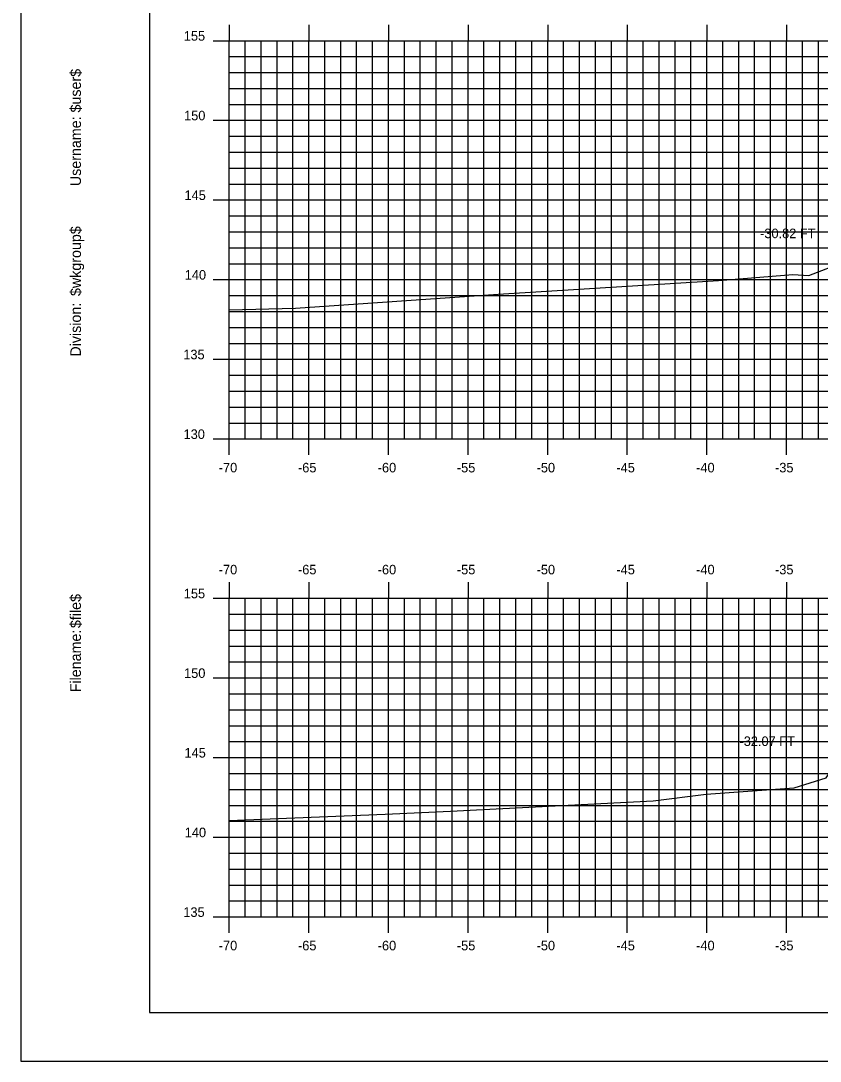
# Model space of a CAD drawing. Extents: x 1143863 to 1144033, y 608981 to 609091.
# Drawn here: x 1143863.5 to 1143913.7, y 608981.3 to 609046.6 of the extents above; entities that cross this region are included whole.
import ezdxf

# ---------------------------------------------------------------- set-up
doc = ezdxf.new("R2010")
doc.units = 0
for name, color, linetype in [('BORDER', 7, 'Continuous'), ('D_Text_Standard', 7, 'Continuous'), ('H_V ANNOTATION', 7, 'Continuous'), ('MAJOR', 7, 'Continuous'), ('MINOR', 7, 'Continuous'), ('PLOT BOUNDARY', 7, 'Continuous'), ('S_Roadway_Centerline', 7, 'Continuous')]:
    doc.layers.add(name, color=color, linetype=linetype)

msp = doc.modelspace()

# ---------------------------------------------------------------- linework, layer by layer
at = {"layer": 'BORDER'}
msp.add_lwpolyline([(1143871.593, 608984.335), (1144031.593, 608984.335), (1144031.593, 609089.335), (1143871.593, 609089.335)], close=True, dxfattribs=at)
at = {"layer": 'MAJOR'}
for p, q in [((1143876.593, 609046.337), (1143876.593, 609045.335)), ((1143881.593, 609046.337), (1143881.593, 609045.335)), ((1143886.593, 609046.337), (1143886.593, 609045.335)), ((1143891.593, 609046.337), (1143891.593, 609045.335)), ((1143896.593, 609046.337), (1143896.593, 609045.335)), ((1143901.593, 609046.337), (1143901.593, 609045.335)), ((1143906.593, 609046.337), (1143906.593, 609045.335)), ((1143911.593, 609046.337), (1143911.593, 609045.335)), ((1143875.591, 609045.335), (1143876.593, 609045.335)), ((1143876.593, 609045.335), (1144016.593, 609045.335)), ((1143876.593, 609020.335), (1143876.593, 609045.335)), ((1143876.593, 609020.335), (1143876.593, 609045.335)), ((1143876.593, 609045.335), (1144016.593, 609045.335)), ((1143881.593, 609020.335), (1143881.593, 609045.335)), ((1143886.593, 609020.335), (1143886.593, 609045.335)), ((1143891.593, 609020.335), (1143891.593, 609045.335)), ((1143896.593, 609020.335), (1143896.593, 609045.335)), ((1143901.593, 609020.335), (1143901.593, 609045.335)), ((1143906.593, 609020.335), (1143906.593, 609045.335)), ((1143911.593, 609020.335), (1143911.593, 609045.335)), ((1143875.591, 609040.335), (1143876.593, 609040.335)), ((1143876.593, 609040.335), (1144016.593, 609040.335)), ((1143875.591, 609035.335), (1143876.593, 609035.335)), ((1143876.593, 609035.335), (1144016.593, 609035.335)), ((1143875.591, 609030.335), (1143876.593, 609030.335)), ((1143876.593, 609030.335), (1144016.593, 609030.335)), ((1143875.591, 609025.335), (1143876.593, 609025.335)), ((1143876.593, 609025.335), (1144016.593, 609025.335)), ((1143875.591, 609020.335), (1143876.593, 609020.335)), ((1143876.593, 609020.335), (1144016.593, 609020.335)), ((1143876.593, 609020.335), (1144016.593, 609020.335)), ((1143876.593, 609019.333), (1143876.593, 609020.335)), ((1143881.593, 609019.333), (1143881.593, 609020.335)), ((1143886.593, 609019.333), (1143886.593, 609020.335)), ((1143891.593, 609019.333), (1143891.593, 609020.335)), ((1143896.593, 609019.333), (1143896.593, 609020.335)), ((1143901.593, 609019.333), (1143901.593, 609020.335)), ((1143906.593, 609019.333), (1143906.593, 609020.335)), ((1143911.593, 609019.333), (1143911.593, 609020.335)), ((1143876.593, 609011.337), (1143876.593, 609010.335)), ((1143881.593, 609011.337), (1143881.593, 609010.335)), ((1143886.593, 609011.337), (1143886.593, 609010.335)), ((1143891.593, 609011.337), (1143891.593, 609010.335)), ((1143896.593, 609011.337), (1143896.593, 609010.335)), ((1143901.593, 609011.337), (1143901.593, 609010.335)), ((1143906.593, 609011.337), (1143906.593, 609010.335)), ((1143911.593, 609011.337), (1143911.593, 609010.335)), ((1143875.591, 609010.335), (1143876.593, 609010.335)), ((1143876.593, 609010.335), (1144016.593, 609010.335)), ((1143876.593, 608990.335), (1143876.593, 609010.335)), ((1143876.593, 608990.335), (1143876.593, 609010.335)), ((1143876.593, 609010.335), (1144016.593, 609010.335)), ((1143881.593, 608990.335), (1143881.593, 609010.335)), ((1143886.593, 608990.335), (1143886.593, 609010.335)), ((1143891.593, 608990.335), (1143891.593, 609010.335)), ((1143896.593, 608990.335), (1143896.593, 609010.335)), ((1143901.593, 608990.335), (1143901.593, 609010.335)), ((1143906.593, 608990.335), (1143906.593, 609010.335)), ((1143911.593, 608990.335), (1143911.593, 609010.335)), ((1143875.591, 609005.335), (1143876.593, 609005.335)), ((1143876.593, 609005.335), (1144016.593, 609005.335)), ((1143875.591, 609000.335), (1143876.593, 609000.335)), ((1143876.593, 609000.335), (1144016.593, 609000.335)), ((1143875.591, 608995.335), (1143876.593, 608995.335)), ((1143876.593, 608995.335), (1144016.593, 608995.335)), ((1143875.591, 608990.335), (1143876.593, 608990.335)), ((1143876.593, 608990.335), (1144016.593, 608990.335)), ((1143876.593, 608990.335), (1144016.593, 608990.335)), ((1143876.593, 608989.333), (1143876.593, 608990.335)), ((1143881.593, 608989.333), (1143881.593, 608990.335)), ((1143886.593, 608989.333), (1143886.593, 608990.335)), ((1143891.593, 608989.333), (1143891.593, 608990.335)), ((1143896.593, 608989.333), (1143896.593, 608990.335)), ((1143901.593, 608989.333), (1143901.593, 608990.335)), ((1143906.593, 608989.333), (1143906.593, 608990.335)), ((1143911.593, 608989.333), (1143911.593, 608990.335))]:
    msp.add_line(p, q, dxfattribs=at)
at = {"layer": 'MINOR'}
for p, q in [((1143877.593, 609020.335), (1143877.593, 609045.335)), ((1143878.593, 609020.335), (1143878.593, 609045.335)), ((1143879.593, 609020.335), (1143879.593, 609045.335)), ((1143880.593, 609020.335), (1143880.593, 609045.335)), ((1143882.593, 609020.335), (1143882.593, 609045.335)), ((1143883.593, 609020.335), (1143883.593, 609045.335)), ((1143884.593, 609020.335), (1143884.593, 609045.335)), ((1143885.593, 609020.335), (1143885.593, 609045.335)), ((1143887.593, 609020.335), (1143887.593, 609045.335)), ((1143888.593, 609020.335), (1143888.593, 609045.335)), ((1143889.593, 609020.335), (1143889.593, 609045.335)), ((1143890.593, 609020.335), (1143890.593, 609045.335)), ((1143892.593, 609020.335), (1143892.593, 609045.335)), ((1143893.593, 609020.335), (1143893.593, 609045.335)), ((1143894.593, 609020.335), (1143894.593, 609045.335)), ((1143895.593, 609020.335), (1143895.593, 609045.335)), ((1143897.593, 609020.335), (1143897.593, 609045.335)), ((1143898.593, 609020.335), (1143898.593, 609045.335)), ((1143899.593, 609020.335), (1143899.593, 609045.335)), ((1143900.593, 609020.335), (1143900.593, 609045.335)), ((1143902.593, 609020.335), (1143902.593, 609045.335)), ((1143903.593, 609020.335), (1143903.593, 609045.335)), ((1143904.593, 609020.335), (1143904.593, 609045.335)), ((1143905.593, 609020.335), (1143905.593, 609045.335)), ((1143907.593, 609020.335), (1143907.593, 609045.335)), ((1143908.593, 609020.335), (1143908.593, 609045.335)), ((1143909.593, 609020.335), (1143909.593, 609045.335)), ((1143910.593, 609020.335), (1143910.593, 609045.335)), ((1143912.593, 609020.335), (1143912.593, 609045.335)), ((1143913.593, 609020.335), (1143913.593, 609045.335)), ((1143876.593, 609044.335), (1144016.593, 609044.335)), ((1143876.593, 609044.335), (1143877.595, 609044.335)), ((1143876.593, 609043.335), (1144016.593, 609043.335)), ((1143876.593, 609043.335), (1143877.595, 609043.335)), ((1143876.593, 609042.335), (1144016.593, 609042.335)), ((1143876.593, 609042.335), (1143877.595, 609042.335)), ((1143876.593, 609041.335), (1144016.593, 609041.335)), ((1143876.593, 609041.335), (1143877.595, 609041.335)), ((1143876.593, 609039.335), (1144016.593, 609039.335)), ((1143876.593, 609039.335), (1143877.595, 609039.335)), ((1143876.593, 609038.335), (1144016.593, 609038.335)), ((1143876.593, 609038.335), (1143877.595, 609038.335)), ((1143876.593, 609037.335), (1144016.593, 609037.335)), ((1143876.593, 609037.335), (1143877.595, 609037.335)), ((1143876.593, 609036.335), (1144016.593, 609036.335)), ((1143876.593, 609036.335), (1143877.595, 609036.335)), ((1143876.593, 609034.335), (1144016.593, 609034.335)), ((1143876.593, 609034.335), (1143877.595, 609034.335)), ((1143876.593, 609033.335), (1144016.593, 609033.335)), ((1143876.593, 609033.335), (1143877.595, 609033.335)), ((1143876.593, 609032.335), (1144016.593, 609032.335)), ((1143876.593, 609032.335), (1143877.595, 609032.335)), ((1143876.593, 609031.335), (1144016.593, 609031.335)), ((1143876.593, 609031.335), (1143877.595, 609031.335)), ((1143876.593, 609029.335), (1144016.593, 609029.335)), ((1143876.593, 609029.335), (1143877.595, 609029.335)), ((1143876.593, 609028.335), (1144016.593, 609028.335)), ((1143876.593, 609028.335), (1143877.595, 609028.335)), ((1143876.593, 609027.335), (1144016.593, 609027.335)), ((1143876.593, 609027.335), (1143877.595, 609027.335)), ((1143876.593, 609026.335), (1144016.593, 609026.335)), ((1143876.593, 609026.335), (1143877.595, 609026.335)), ((1143876.593, 609024.335), (1144016.593, 609024.335)), ((1143876.593, 609024.335), (1143877.595, 609024.335)), ((1143876.593, 609023.335), (1144016.593, 609023.335)), ((1143876.593, 609023.335), (1143877.595, 609023.335)), ((1143876.593, 609022.335), (1144016.593, 609022.335)), ((1143876.593, 609022.335), (1143877.595, 609022.335)), ((1143876.593, 609021.335), (1144016.593, 609021.335)), ((1143876.593, 609021.335), (1143877.595, 609021.335)), ((1143877.593, 608990.335), (1143877.593, 609010.335)), ((1143878.593, 608990.335), (1143878.593, 609010.335)), ((1143879.593, 608990.335), (1143879.593, 609010.335)), ((1143880.593, 608990.335), (1143880.593, 609010.335)), ((1143882.593, 608990.335), (1143882.593, 609010.335)), ((1143883.593, 608990.335), (1143883.593, 609010.335)), ((1143884.593, 608990.335), (1143884.593, 609010.335)), ((1143885.593, 608990.335), (1143885.593, 609010.335)), ((1143887.593, 608990.335), (1143887.593, 609010.335)), ((1143888.593, 608990.335), (1143888.593, 609010.335)), ((1143889.593, 608990.335), (1143889.593, 609010.335)), ((1143890.593, 608990.335), (1143890.593, 609010.335)), ((1143892.593, 608990.335), (1143892.593, 609010.335)), ((1143893.593, 608990.335), (1143893.593, 609010.335)), ((1143894.593, 608990.335), (1143894.593, 609010.335)), ((1143895.593, 608990.335), (1143895.593, 609010.335)), ((1143897.593, 608990.335), (1143897.593, 609010.335)), ((1143898.593, 608990.335), (1143898.593, 609010.335)), ((1143899.593, 608990.335), (1143899.593, 609010.335)), ((1143900.593, 608990.335), (1143900.593, 609010.335)), ((1143902.593, 608990.335), (1143902.593, 609010.335)), ((1143903.593, 608990.335), (1143903.593, 609010.335)), ((1143904.593, 608990.335), (1143904.593, 609010.335)), ((1143905.593, 608990.335), (1143905.593, 609010.335)), ((1143907.593, 608990.335), (1143907.593, 609010.335)), ((1143908.593, 608990.335), (1143908.593, 609010.335)), ((1143909.593, 608990.335), (1143909.593, 609010.335)), ((1143910.593, 608990.335), (1143910.593, 609010.335)), ((1143912.593, 608990.335), (1143912.593, 609010.335)), ((1143913.593, 608990.335), (1143913.593, 609010.335)), ((1143876.593, 609009.335), (1144016.593, 609009.335)), ((1143876.593, 609009.335), (1143877.595, 609009.335)), ((1143876.593, 609008.335), (1144016.593, 609008.335)), ((1143876.593, 609008.335), (1143877.595, 609008.335)), ((1143876.593, 609007.335), (1144016.593, 609007.335)), ((1143876.593, 609007.335), (1143877.595, 609007.335)), ((1143876.593, 609006.335), (1144016.593, 609006.335)), ((1143876.593, 609006.335), (1143877.595, 609006.335)), ((1143876.593, 609004.335), (1144016.593, 609004.335)), ((1143876.593, 609004.335), (1143877.595, 609004.335)), ((1143876.593, 609003.335), (1144016.593, 609003.335)), ((1143876.593, 609003.335), (1143877.595, 609003.335)), ((1143876.593, 609002.335), (1144016.593, 609002.335)), ((1143876.593, 609002.335), (1143877.595, 609002.335)), ((1143876.593, 609001.335), (1144016.593, 609001.335)), ((1143876.593, 609001.335), (1143877.595, 609001.335)), ((1143876.593, 608999.335), (1144016.593, 608999.335)), ((1143876.593, 608999.335), (1143877.595, 608999.335)), ((1143876.593, 608998.335), (1144016.593, 608998.335)), ((1143876.593, 608998.335), (1143877.595, 608998.335)), ((1143876.593, 608997.335), (1144016.593, 608997.335)), ((1143876.593, 608997.335), (1143877.595, 608997.335)), ((1143876.593, 608996.335), (1144016.593, 608996.335)), ((1143876.593, 608996.335), (1143877.595, 608996.335)), ((1143876.593, 608994.335), (1144016.593, 608994.335)), ((1143876.593, 608994.335), (1143877.595, 608994.335)), ((1143876.593, 608993.335), (1144016.593, 608993.335)), ((1143876.593, 608993.335), (1143877.595, 608993.335)), ((1143876.593, 608992.335), (1144016.593, 608992.335)), ((1143876.593, 608992.335), (1143877.595, 608992.335)), ((1143876.593, 608991.335), (1144016.593, 608991.335)), ((1143876.593, 608991.335), (1143877.595, 608991.335))]:
    msp.add_line(p, q, dxfattribs=at)
at = {"layer": 'PLOT BOUNDARY'}
msp.add_lwpolyline([(1143863.5, 608981.276), (1144033.5, 608981.276), (1144033.5, 609091.276), (1143863.5, 609091.276)], close=True, dxfattribs=at)
at = {"layer": 'S_Roadway_Centerline'}
for points in [[(1143876.593, 609028.445), (1143880.764, 609028.537), (1143893.48, 609029.427), (1143907.327, 609030.275), (1143911.989, 609030.655), (1143912.996, 609030.602), (1143915.271, 609031.477), (1143918.046, 609032.388), (1143921.473, 609032.795), (1143921.72, 609032.822), (1143931.839, 609033.205), (1143932.613, 609033.238), (1143933.341, 609033.203), (1143943.019, 609032.935), (1143943.336, 609032.897), (1143946.452, 609032.294), (1143947.313, 609031.983), (1143956.366, 609028.867), (1143960.542, 609028.707), (1143973.447, 609027.173), (1143980.648, 609027.329), (1143988.842, 609027.119), (1144003.679, 609028.03), (1144016.593, 609029.026)], [(1143876.593, 608996.389), (1143886.383, 608996.779), (1143890.479, 608996.962), (1143903.211, 608997.625), (1143906.538, 608998.034), (1143912.067, 608998.435), (1143914.081, 608999.053), (1143914.282, 608999.331), (1143916.775, 608999.597), (1143917.269, 608999.647), (1143926.978, 609000.028), (1143928.239, 609000.064), (1143929.388, 608999.997), (1143939.153, 608999.508), (1143939.515, 608999.476), (1143943.549, 608998.987), (1143943.896, 608998.914), (1143948.361, 608998.006), (1143948.831, 608998.25), (1143964.691, 608999.12), (1143966.29, 608999.203), (1143976.108, 608999.128)]]:
    msp.add_lwpolyline(points, dxfattribs=at)

# ---------------------------------------------------------------- texts
at = {"layer": 'BORDER'}
for s, p in [('$user$', (1143867.278, 609040.827)), ('Username:', (1143867.278, 609036.203)), ('$wkgroup$', (1143867.278, 609029.305)), ('Division:', (1143867.278, 609025.501)), ('$file$', (1143867.278, 609008.461)), ('Filename:', (1143867.278, 609004.433))]:
    msp.add_text(s, height=0.6696, rotation=90, dxfattribs=at).set_placement(p)
at = {"layer": 'D_Text_Standard'}
for s, p in [('-30.82 FT', (1143909.935, 609032.938)), ('-32.07 FT', (1143908.64, 609001.061))]:
    msp.add_text(s, height=0.6, dxfattribs=at).set_placement(p)
at = {"layer": 'H_V ANNOTATION'}
for s, p in [('155', (1143873.739, 609045.335)), ('150', (1143873.755, 609040.335)), ('145', (1143873.782, 609035.335)), ('140', (1143873.798, 609030.335)), ('135', (1143873.707, 609025.335)), ('130', (1143873.723, 609020.335)), ('-70', (1143875.934, 609018.235)), ('-65', (1143880.91, 609018.235)), ('-60', (1143885.918, 609018.235)), ('-55', (1143890.889, 609018.235)), ('-50', (1143895.897, 609018.235)), ('-45', (1143900.91, 609018.235)), ('-40', (1143905.918, 609018.235)), ('-35', (1143910.873, 609018.235)), ('-70', (1143875.934, 609011.835)), ('-65', (1143880.91, 609011.835)), ('-60', (1143885.918, 609011.835)), ('-55', (1143890.889, 609011.835)), ('-50', (1143895.897, 609011.835)), ('-45', (1143900.91, 609011.835)), ('-40', (1143905.918, 609011.835)), ('-35', (1143910.873, 609011.835)), ('155', (1143873.739, 609010.335)), ('150', (1143873.755, 609005.335)), ('145', (1143873.782, 609000.335)), ('140', (1143873.798, 608995.335)), ('135', (1143873.707, 608990.335)), ('-70', (1143875.934, 608988.235)), ('-65', (1143880.91, 608988.235)), ('-60', (1143885.918, 608988.235)), ('-55', (1143890.889, 608988.235)), ('-50', (1143895.897, 608988.235)), ('-45', (1143900.91, 608988.235)), ('-40', (1143905.918, 608988.235)), ('-35', (1143910.873, 608988.235))]:
    msp.add_text(s, height=0.6, dxfattribs=at).set_placement(p)
at = {"layer": 'MAJOR'}
for p in [(1143876.588, 609020.335), (1143876.588, 608990.335)]:
    msp.add_text('-', height=0.006, dxfattribs=at).set_placement(p)

doc.saveas('drawing.dxf')
